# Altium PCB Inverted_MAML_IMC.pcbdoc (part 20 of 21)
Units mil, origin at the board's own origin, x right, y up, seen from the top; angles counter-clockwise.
Board outline 7677.1 x 6771.6 mil, 6 copper layers (Top Layer, Inner1, Inner2, Inner3, Inner4, Bottom Layer), stack 60.7 mil thick; 2732 components, 1531 nets, 7765 pads, 3705 vias.
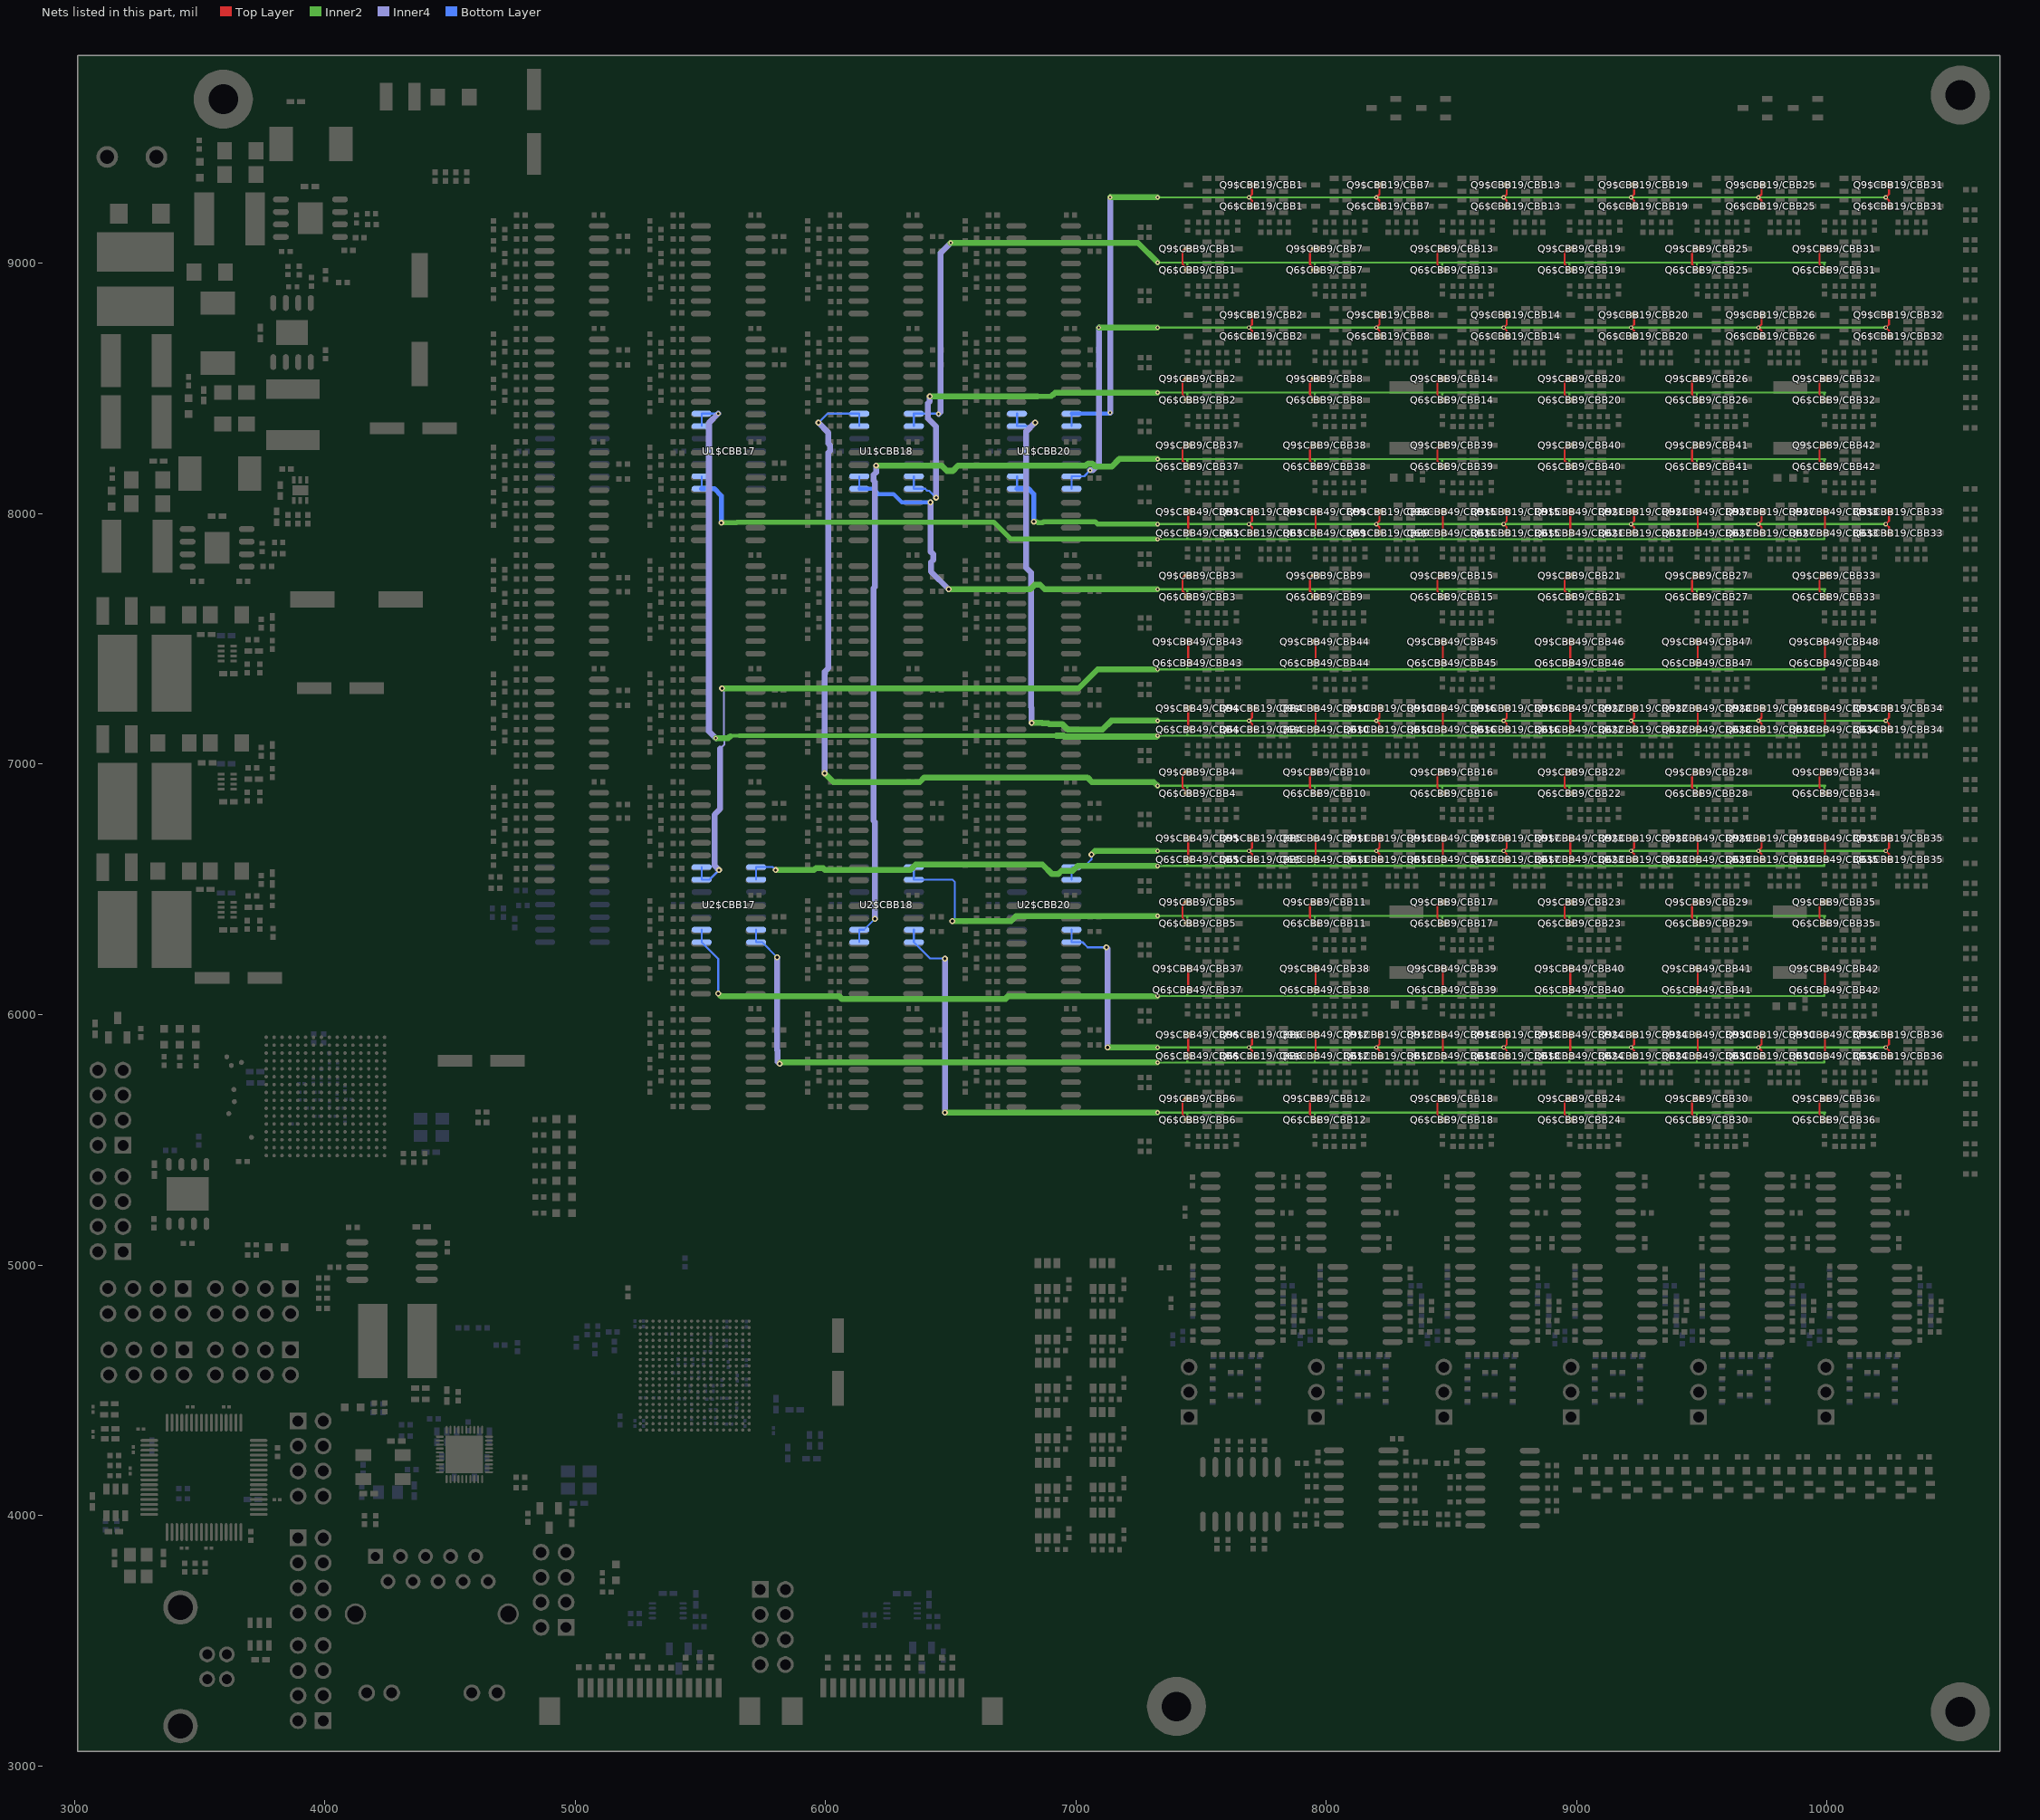
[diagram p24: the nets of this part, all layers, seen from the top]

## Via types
v1: diameter 17.7, hole 7.9, Top Layer to Bottom Layer, 3373 vias
v2: diameter 13.8, hole 7.9, Top Layer to Bottom Layer, 287 vias
v3: diameter 23.6, hole 11.8, Top Layer to Bottom Layer, 45 vias

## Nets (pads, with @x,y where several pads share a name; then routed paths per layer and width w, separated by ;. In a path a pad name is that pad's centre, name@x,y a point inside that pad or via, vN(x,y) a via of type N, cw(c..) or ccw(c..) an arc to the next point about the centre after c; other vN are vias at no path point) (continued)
W_M1_ROW3: Q6$CBB49/CBB3.3 Q6$CBB49/CBB9.3 Q6$CBB49/CBB15.3 Q6$CBB49/CBB21.3 Q6$CBB49/CBB27.3 Q6$CBB49/CBB33.3 Q9$CBB49/CBB3.3 Q9$CBB49/CBB9.3 Q9$CBB49/CBB15.3 Q9$CBB49/CBB21.3 Q9$CBB49/CBB27.3 Q9$CBB49/CBB33.3 U1$CBB17.8 U1$CBB17.9 | length 5355.6
  Top Layer w7.9: v1(7445.3,7923.7) 7448.8,7927.2 7448.8,7969 7448.4,7969.4 7448.4,7984.2 7448.8,7984.6 Q9$CBB49/CBB3.3@7448.8,8008.7 ; v1(7954,7923.7) 7957.5,7927.2 7957.5,7969 7957.1,7969.4 7957.1,7984.2 7957.5,7984.6 Q9$CBB49/CBB9.3@7957.5,8008.7 ; v1(8462.7,7923.7) 8466.2,7927.2 8466.2,7969 8465.8,7969.4 8465.8,7984.1 8466.2,7984.5 Q9$CBB49/CBB15.3@8466.2,8008.7 ; v1(8971.4,7923.7) 8974.9,7927.2 8974.9,7969 8974.5,7969.4 8974.5,7984.2 8974.9,7984.6 Q9$CBB49/CBB21.3@8974.9,8008.7 ; v1(9480.1,7923.7) 9483.6,7927.2 9483.6,7969 9483.2,7969.4 9483.2,7984.2 9483.6,7984.6 Q9$CBB49/CBB27.3@9483.6,8008.7 ; v1(9988.8,7923.7) 9992.3,7927.2 9992.3,7969 9991.9,7969.4 9991.9,7984.2 9992.3,7984.6 Q9$CBB49/CBB33.3@9992.3,8008.7
  Inner2 w7.9: v1(7326.2,7898.7) 7445.9,7898.7 ; v1(7445.3,7923.7) 7445.3,7899.3 7445.9,7898.7 ; v1(7954,7923.7) 7954,7899.3 7954.6,7898.7 ; v1(8462.7,7923.7) 8462.7,7899.3 8463.2,7898.7 ; v1(8971.4,7923.7) 8971.4,7899.3 8972,7898.7 ; v1(9480.1,7923.7) 9480.1,7899.3 9480.7,7898.7 ; v1(9988.8,7923.7) 9988.8,7899.3 9989.4,7898.7 9480.7,7898.7 ; 7445.9,7898.7 7954.6,7898.7 ; 7954.6,7898.7 8463.2,7898.7 ; 8463.2,7898.7 8972,7898.7 ; 8972,7898.7 9480.7,7898.7
  Inner2 w19.7: v3(5583.9,7963.7) 5644.1,7963.7 5647.3,7966.9 6671.8,7966.9 6740,7898.7 v1(7326.2,7898.7)
  Bottom Layer w7.9: U1$CBB17.8@5505.4,8100.1 U1$CBB17.9@5505.4,8150.1
  Bottom Layer w19.7: U1$CBB17.8@5505.4,8100.1 5555.8,8100.1 5583.9,8072 v3(5583.9,7963.7)
W_M1_ROW4: Q6$CBB49/CBB4.3 Q6$CBB49/CBB10.3 Q6$CBB49/CBB16.3 Q6$CBB49/CBB22.3 Q6$CBB49/CBB28.3 Q6$CBB49/CBB34.3 Q9$CBB49/CBB4.3 Q9$CBB49/CBB10.3 Q9$CBB49/CBB16.3 Q9$CBB49/CBB22.3 Q9$CBB49/CBB28.3 Q9$CBB49/CBB34.3 U1$CBB17.13 U1$CBB17.14 | length 6543.5
  Top Layer w7.9: v1(7445.3,7138.7) 7448.8,7142.2 7448.8,7184 7448.4,7184.4 7448.4,7199.2 7448.8,7199.6 Q9$CBB49/CBB4.3@7448.8,7223.7 ; v1(7954,7138.7) 7957.5,7142.2 7957.5,7184 7957.1,7184.4 7957.1,7199.2 7957.5,7199.6 Q9$CBB49/CBB10.3@7957.5,7223.7 ; v1(8462.7,7138.7) 8466.2,7142.2 8466.2,7184 8465.8,7184.4 8465.8,7199.1 8466.2,7199.5 Q9$CBB49/CBB16.3@8466.2,7223.7 ; v1(8971.4,7138.7) 8974.9,7142.2 8974.9,7184 8974.5,7184.4 8974.5,7199.2 8974.9,7199.6 Q9$CBB49/CBB22.3@8974.9,7223.7 ; v1(9480.1,7138.7) 9483.6,7142.2 9483.6,7184 9483.2,7184.4 9483.2,7199.2 9483.6,7199.6 Q9$CBB49/CBB28.3@9483.6,7223.7 ; v1(9988.8,7138.7) 9992.3,7142.2 9992.3,7184 9991.9,7184.4 9991.9,7199.2 9992.3,7199.6 Q9$CBB49/CBB34.3@9992.3,7223.7
  Inner2 w7.9: v1(7326.2,7113.7) 7445.9,7113.7 ; v1(7445.3,7138.7) 7445.3,7114.3 7445.9,7113.7 ; v1(7954,7138.7) 7954,7114.3 7954.6,7113.7 ; v1(8462.7,7138.7) 8462.7,7114.3 8463.2,7113.7 ; v1(8971.4,7138.7) 8971.4,7114.3 8972,7113.7 ; v1(9480.1,7138.7) 9480.1,7114.3 9480.7,7113.7 ; v1(9988.8,7138.7) 9988.8,7114.3 9989.4,7113.7 9480.7,7113.7 ; 7445.9,7113.7 7954.6,7113.7 ; 7954.6,7113.7 8463.2,7113.7 ; 8463.2,7113.7 8972,7113.7 ; 8972,7113.7 9480.7,7113.7
  Inner2 w15.7: 5622.1,7113.7 5657.1,7113.7
  Inner2 w19.7: 5657.1,7113.7 6922.1,7113.7
  Inner2 w23.6: v1(5562.1,7103.7) 5612.1,7103.7 5620.1,7111.7 ; 6922.1,7113.7 6951.6,7113.7 6955.3,7110.1 7322.6,7110.1 v1(7326.2,7113.7)
  Inner4 w23.6: v1(5562.1,7103.7) 5534.8,7131.1 5534.8,8362.7 v1(5572.1,8400.1)
  Bottom Layer w7.9: U1$CBB17.13@5505.4,8350.1 U1$CBB17.14@5505.4,8400.1 v1(5572.1,8400.1)
W_M1_ROW5: Q6$CBB49/CBB5.3 Q6$CBB49/CBB11.3 Q6$CBB49/CBB17.3 Q6$CBB49/CBB23.3 Q6$CBB49/CBB29.3 Q6$CBB49/CBB35.3 Q9$CBB49/CBB5.3 Q9$CBB49/CBB11.3 Q9$CBB49/CBB17.3 Q9$CBB49/CBB23.3 Q9$CBB49/CBB29.3 Q9$CBB49/CBB35.3 U2$CBB17.1 U2$CBB17.2 | length 5038.7
  Top Layer w7.9: v1(7445.3,6618.7) 7448.8,6622.2 7448.8,6664 7448.4,6664.4 7448.4,6679.2 7448.8,6679.6 Q9$CBB49/CBB5.3@7448.8,6703.7 ; v1(7954,6618.7) 7957.5,6622.2 7957.5,6664 7957.1,6664.4 7957.1,6679.2 7957.5,6679.6 Q9$CBB49/CBB11.3@7957.5,6703.7 ; v1(8462.7,6618.7) 8466.2,6622.2 8466.2,6664 8465.8,6664.4 8465.8,6679.1 8466.2,6679.5 Q9$CBB49/CBB17.3@8466.2,6703.7 ; v1(8971.4,6618.7) 8974.9,6622.2 8974.9,6664 8974.5,6664.4 8974.5,6679.2 8974.9,6679.6 Q9$CBB49/CBB23.3@8974.9,6703.7 ; v1(9480.1,6618.7) 9483.6,6622.2 9483.6,6664 9483.2,6664.4 9483.2,6679.2 9483.6,6679.6 Q9$CBB49/CBB29.3@9483.6,6703.7 ; v1(9988.8,6618.7) 9992.3,6622.2 9992.3,6664 9991.9,6664.4 9991.9,6679.2 9992.3,6679.6 Q9$CBB49/CBB35.3@9992.3,6703.7
  Inner2 w7.9: v1(7326.2,6593.7) 7445.9,6593.7 ; v1(7445.3,6618.7) 7445.3,6594.3 7445.9,6593.7 ; v1(7954,6618.7) 7954,6594.3 7954.6,6593.7 ; v1(8462.7,6618.7) 8462.7,6594.3 8463.2,6593.7 ; v1(8971.4,6618.7) 8971.4,6594.3 8972,6593.7 ; v1(9480.1,6618.7) 9480.1,6594.3 9480.7,6593.7 ; v1(9988.8,6618.7) 9988.8,6594.3 9989.4,6593.7 9480.7,6593.7 ; 7445.9,6593.7 7954.6,6593.7 ; 7954.6,6593.7 8463.2,6593.7 ; 8463.2,6593.7 8972,6593.7 ; 8972,6593.7 9480.7,6593.7
  Inner2 w23.6: v3(5800.7,6577) 5953.6,6577 5961.8,6585.3 5991.2,6585.3 5999.4,6577 6338.3,6577 6360.1,6598.9 6866.8,6598.9 6904.9,6560.7 6929,6560.7 6942.1,6573.7 6987.1,6573.7 7007.1,6593.7 v1(7326.2,6593.7)
  Bottom Layer w7.9: U2$CBB17.2@5723.4,6539.1 U2$CBB17.1@5723.4,6589.1 5788.7,6589.1 v3(5800.7,6577)
W_M1_ROW6: Q6$CBB49/CBB6.3 Q6$CBB49/CBB12.3 Q6$CBB49/CBB18.3 Q6$CBB49/CBB24.3 Q6$CBB49/CBB30.3 Q6$CBB49/CBB36.3 Q9$CBB49/CBB6.3 Q9$CBB49/CBB12.3 Q9$CBB49/CBB18.3 Q9$CBB49/CBB24.3 Q9$CBB49/CBB30.3 Q9$CBB49/CBB36.3 U2$CBB17.6 U2$CBB17.7 | length 5434.4
  Top Layer w7.9: v1(7445.3,5833.7) 7448.8,5837.2 7448.8,5879 7448.4,5879.4 7448.4,5894.2 7448.8,5894.6 Q9$CBB49/CBB6.3@7448.8,5918.7 ; v1(7954,5833.7) 7957.5,5837.2 7957.5,5879 7957.1,5879.4 7957.1,5894.2 7957.5,5894.6 Q9$CBB49/CBB12.3@7957.5,5918.7 ; v1(8462.7,5833.7) 8466.2,5837.2 8466.2,5879 8465.8,5879.4 8465.8,5894.1 8466.2,5894.5 Q9$CBB49/CBB18.3@8466.2,5918.7 ; v1(8971.4,5833.7) 8974.9,5837.2 8974.9,5879 8974.5,5879.4 8974.5,5894.2 8974.9,5894.6 Q9$CBB49/CBB24.3@8974.9,5918.7 ; v1(9480.1,5833.7) 9483.6,5837.2 9483.6,5879 9483.2,5879.4 9483.2,5894.2 9483.6,5894.6 Q9$CBB49/CBB30.3@9483.6,5918.7 ; v1(9988.8,5833.7) 9992.3,5837.2 9992.3,5879 9991.9,5879.4 9991.9,5894.2 9992.3,5894.6 Q9$CBB49/CBB36.3@9992.3,5918.7
  Inner2 w7.9: v1(7326.2,5808.7) 7445.9,5808.7 ; v1(7445.3,5833.7) 7445.3,5809.3 7445.9,5808.7 ; v1(7954,5833.7) 7954,5809.3 7954.6,5808.7 ; v1(8462.7,5833.7) 8462.7,5809.3 8463.2,5808.7 ; v1(8971.4,5833.7) 8971.4,5809.3 8972,5808.7 ; v1(9480.1,5833.7) 9480.1,5809.3 9480.7,5808.7 ; v1(9988.8,5833.7) 9988.8,5809.3 9989.4,5808.7 9480.7,5808.7 ; 7445.9,5808.7 7954.6,5808.7 ; 7954.6,5808.7 8463.2,5808.7 ; 8463.2,5808.7 8972,5808.7 ; 8972,5808.7 9480.7,5808.7
  Inner2 w23.6: v3(5817.1,5803.7) 5822.1,5808.7 v1(7326.2,5808.7)
  Inner4 w23.6: v3(5807.1,6228.7) 5807.1,5858.8 5809.3,5856.6 5809.3,5811.5 v3(5817.1,5803.7)
  Bottom Layer w7.9: U2$CBB17.6@5723.4,6339.1 U2$CBB17.7@5723.4,6289.1 5746.8,6289.1 v3(5807.1,6228.7)
W_M1_ROW7: Q6$CBB49/CBB37.3 Q6$CBB49/CBB38.3 Q6$CBB49/CBB39.3 Q6$CBB49/CBB40.3 Q6$CBB49/CBB41.3 Q6$CBB49/CBB42.3 Q9$CBB49/CBB37.3 Q9$CBB49/CBB38.3 Q9$CBB49/CBB39.3 Q9$CBB49/CBB40.3 Q9$CBB49/CBB41.3 Q9$CBB49/CBB42.3 U2$CBB17.8 U2$CBB17.9 | length 5386.7
  Top Layer w7.9: v1(7445.3,6098.7) 7448.8,6102.2 7448.8,6144 7448.4,6144.4 7448.4,6159.2 7448.8,6159.6 Q9$CBB49/CBB37.3@7448.8,6183.7 ; v1(7954,6098.7) 7957.5,6102.2 7957.5,6144 7957.1,6144.4 7957.1,6159.2 7957.5,6159.6 Q9$CBB49/CBB38.3@7957.5,6183.7 ; v1(8462.7,6098.7) 8466.2,6102.2 8466.2,6144 8465.8,6144.4 8465.8,6159.2 8466.2,6159.6 Q9$CBB49/CBB39.3@8466.2,6183.7 ; v1(8971.4,6098.7) 8974.9,6102.2 8974.9,6144 8974.5,6144.4 8974.5,6159.2 8974.9,6159.6 Q9$CBB49/CBB40.3@8974.9,6183.7 ; v1(9480.1,6098.7) 9483.6,6102.2 9483.6,6144 9483.2,6144.4 9483.2,6159.2 9483.6,6159.6 Q9$CBB49/CBB41.3@9483.6,6183.7 ; v1(9988.8,6098.7) 9992.3,6102.2 9992.3,6144 9991.9,6144.4 9991.9,6159.2 9992.3,6159.6 Q9$CBB49/CBB42.3@9992.3,6183.7
  Inner2 w7.9: v1(7326.2,6073.7) 7445.9,6073.7 ; v1(7445.3,6098.7) 7445.3,6074.3 7445.9,6073.7 ; v1(7954,6098.7) 7954,6074.3 7954.6,6073.7 ; v1(8462.7,6098.7) 8462.7,6074.3 8463.3,6073.7 ; v1(8971.4,6098.7) 8971.4,6074.3 8972,6073.7 ; v1(9480.1,6098.7) 9480.1,6074.3 9480.7,6073.7 ; v1(9988.8,6098.7) 9988.8,6074.3 9989.4,6073.7 9480.7,6073.7 ; 7445.9,6073.7 7954.6,6073.7 ; 7954.6,6073.7 8463.3,6073.7 ; 8463.3,6073.7 8972,6073.7 ; 8972,6073.7 9480.7,6073.7
  Inner2 w23.6: v3(5572.1,6083.7) 5582.1,6073.7 6054.2,6073.7 6066.4,6061.5 6541.3,6061.5 6542.8,6063.1 6719.1,6063.1 6729.8,6073.7 v1(7326.2,6073.7)
  Bottom Layer w7.9: U2$CBB17.9@5505.4,6339.1 U2$CBB17.8@5505.4,6289.1 5572.1,6222.3 v3(5572.1,6083.7)
W_M1_ROW8: Q6$CBB49/CBB43.3 Q6$CBB49/CBB44.3 Q6$CBB49/CBB45.3 Q6$CBB49/CBB46.3 Q6$CBB49/CBB47.3 Q6$CBB49/CBB48.3 Q9$CBB49/CBB43.3 Q9$CBB49/CBB44.3 Q9$CBB49/CBB45.3 Q9$CBB49/CBB46.3 Q9$CBB49/CBB47.3 Q9$CBB49/CBB48.3 U2$CBB17.13 U2$CBB17.14 | length 5994.6
  Top Layer w7.9: v1(7445.3,7403.7) 7448.8,7407.2 7448.8,7449 7448.4,7449.4 7448.4,7464.2 7448.8,7464.6 Q9$CBB49/CBB43.3@7448.8,7488.7 ; v1(7954,7403.7) 7957.5,7407.2 7957.5,7449 7957.1,7449.4 7957.1,7464.2 7957.5,7464.6 Q9$CBB49/CBB44.3@7957.5,7488.7 ; v1(8462.7,7403.7) 8466.2,7407.2 8466.2,7449 8465.8,7449.4 8465.8,7464.2 8466.2,7464.6 Q9$CBB49/CBB45.3@8466.2,7488.7 ; v1(8971.4,7403.7) 8974.9,7407.2 8974.9,7449 8974.5,7449.4 8974.5,7464.2 8974.9,7464.6 Q9$CBB49/CBB46.3@8974.9,7488.7 ; v1(9480.1,7403.7) 9483.6,7407.2 9483.6,7449 9483.2,7449.4 9483.2,7464.2 9483.6,7464.6 Q9$CBB49/CBB47.3@9483.6,7488.7 ; v1(9988.8,7403.7) 9992.3,7407.2 9992.3,7449 9991.9,7449.4 9991.9,7464.2 9992.3,7464.6 Q9$CBB49/CBB48.3@9992.3,7488.7
  Inner2 w7.9: v1(7326.2,7378.7) 7445.9,7378.7 ; v1(7445.3,7403.7) 7445.3,7379.3 7445.9,7378.7 ; v1(7954,7403.7) 7954,7379.3 7954.6,7378.7 ; v1(8462.7,7403.7) 8462.7,7379.3 8463.3,7378.7 ; v1(8971.4,7403.7) 8971.4,7379.3 8972,7378.7 ; v1(9480.1,7403.7) 9480.1,7379.3 9480.7,7378.7 ; v1(9988.8,7403.7) 9988.8,7379.3 9989.4,7378.7 9480.7,7378.7 ; 7445.9,7378.7 7954.6,7378.7 ; 7954.6,7378.7 8463.3,7378.7 ; 8463.3,7378.7 8972,7378.7 ; 8972,7378.7 9480.7,7378.7
  Inner2 w23.6: v3(5586.9,7302.8) 7011.2,7302.8 7087.1,7378.7 v1(7326.2,7378.7)
  Inner4 w7.9: 5579.5,7061.4 5596.3,7078.2 5596.3,7112.8 5594.7,7114.3 5594.7,7295 v3(5586.9,7302.8)
  Inner4 w23.6: v3(5574.9,6577) 5557.1,6594.8 5557.1,6798.7 5579.5,6821.1 5579.5,7061.4
  Bottom Layer w7.9: U2$CBB17.14@5505.4,6589.1 U2$CBB17.13@5505.4,6539.1 5536.9,6539.1 v3(5574.9,6577)
W_M2_ROW1: Q6$CBB9/CBB1.3 Q6$CBB9/CBB7.3 Q6$CBB9/CBB13.3 Q6$CBB9/CBB19.3 Q6$CBB9/CBB25.3 Q6$CBB9/CBB31.3 Q9$CBB9/CBB1.3 Q9$CBB9/CBB7.3 Q9$CBB9/CBB13.3 Q9$CBB9/CBB19.3 Q9$CBB9/CBB25.3 Q9$CBB9/CBB31.3 U1$CBB18.1 U1$CBB18.2 | length 5258.8
  Top Layer w7.9: v1(7445.3,8973.5) 7448.5,8973.5 Q6$CBB9/CBB1.3@7448.8,8973.7 7426.2,8996.3 7426.2,9048.7 7436.2,9058.7 Q9$CBB9/CBB1.3@7448.8,9058.7 ; v1(7954,8973.5) 7957.2,8973.5 Q6$CBB9/CBB7.3@7957.5,8973.7 7934.9,8996.3 7934.9,9048.7 7944.9,9058.7 Q9$CBB9/CBB7.3@7957.5,9058.7 ; v1(8462.7,8973.4) 8465.9,8973.4 Q6$CBB9/CBB13.3@8466.2,8973.7 8443.6,8996.3 8443.6,9048.7 8453.6,9058.7 Q9$CBB9/CBB13.3@8466.2,9058.7 ; v1(8971.4,8973.5) 8974.6,8973.5 Q6$CBB9/CBB19.3@8974.9,8973.7 8952.3,8996.3 8952.3,9048.7 8962.3,9058.7 Q9$CBB9/CBB19.3@8974.9,9058.7 ; v1(9480.1,8973.5) 9483.3,8973.5 Q6$CBB9/CBB25.3@9483.6,8973.7 9461,8996.3 9461,9048.7 9471,9058.7 Q9$CBB9/CBB25.3@9483.6,9058.7 ; v1(9988.8,8973.5) 9992,8973.5 Q6$CBB9/CBB31.3@9992.3,8973.7 9969.7,8996.3 9969.7,9048.7 9979.7,9058.7 Q9$CBB9/CBB31.3@9992.3,9058.7
  Inner2 w7.9: v1(7326.2,9003.7) 7449.8,9003.7 ; v1(7445.3,8973.5) 7445.3,8999.2 7449.8,9003.7 ; v1(7954,8973.5) 7954,8999.2 7958.5,9003.7 ; v1(8462.7,8973.4) 8462.7,8999.1 8467.2,9003.7 ; v1(8971.4,8973.5) 8971.4,8999.2 8975.9,9003.7 ; v1(9480.1,8973.5) 9480.1,8999.2 9484.6,9003.7 ; v1(9988.8,8973.5) 9988.8,8999.2 9993.3,9003.7 9484.6,9003.7 ; 7449.8,9003.7 7958.5,9003.7 ; 7958.5,9003.7 8975.9,9003.7 ; 8975.9,9003.7 9484.6,9003.7
  Inner2 w23.6: v1(6500.3,9082.1) 6500.6,9081.8 7248.1,9081.8 v1(7326.2,9003.7)
  Inner4 w23.6: v1(6452.1,8398.7) 6459.5,8406.1 6459.5,9041.3 v1(6500.3,9082.1)
  Bottom Layer w7.9: U1$CBB18.2@6353.3,8350.1 U1$CBB18.1@6353.3,8400.1 6450.8,8400.1 v1(6452.1,8398.7)
W_M2_ROW2: Q6$CBB9/CBB2.3 Q6$CBB9/CBB8.3 Q6$CBB9/CBB14.3 Q6$CBB9/CBB20.3 Q6$CBB9/CBB26.3 Q6$CBB9/CBB32.3 Q9$CBB9/CBB2.3 Q9$CBB9/CBB8.3 Q9$CBB9/CBB14.3 Q9$CBB9/CBB20.3 Q9$CBB9/CBB26.3 Q9$CBB9/CBB32.3 U1$CBB18.6 U1$CBB18.7 | length 5037.4
  Top Layer w7.9: v1(7445.3,8453.5) 7448.5,8453.5 Q6$CBB9/CBB2.3@7448.8,8453.7 7426.2,8476.3 7426.2,8528.7 7436.2,8538.7 Q9$CBB9/CBB2.3@7448.8,8538.7 ; v1(7954,8453.5) 7957.2,8453.5 Q6$CBB9/CBB8.3@7957.5,8453.7 7934.9,8476.3 7934.9,8528.7 7944.9,8538.7 Q9$CBB9/CBB8.3@7957.5,8538.7 ; v1(8462.7,8453.4) 8465.9,8453.4 Q6$CBB9/CBB14.3@8466.2,8453.7 8443.6,8476.3 8443.6,8528.7 8453.6,8538.7 Q9$CBB9/CBB14.3@8466.2,8538.7 ; v1(8971.4,8453.5) 8974.6,8453.5 Q6$CBB9/CBB20.3@8974.9,8453.7 8952.3,8476.3 8952.3,8528.7 8962.3,8538.7 Q9$CBB9/CBB20.3@8974.9,8538.7 ; v1(9480.1,8453.5) 9483.3,8453.5 Q6$CBB9/CBB26.3@9483.6,8453.7 9461,8476.3 9461,8528.7 9471,8538.7 Q9$CBB9/CBB26.3@9483.6,8538.7 ; v1(9988.8,8453.5) 9992,8453.5 Q6$CBB9/CBB32.3@9992.3,8453.7 9969.7,8476.3 9969.7,8528.7 9979.7,8538.7 Q9$CBB9/CBB32.3@9992.3,8538.7
  Inner2 w7.9: v1(7326.2,8483.7) 7449.8,8483.7 ; v1(7445.3,8453.5) 7445.3,8479.2 7449.8,8483.7 ; v1(7954,8453.5) 7954,8479.2 7958.5,8483.7 ; v1(8462.7,8453.4) 8462.7,8479.1 8467.2,8483.7 ; v1(8971.4,8453.5) 8971.4,8479.2 8975.9,8483.7 ; v1(9480.1,8453.5) 9480.1,8479.2 9484.6,8483.7 ; v1(9988.8,8453.5) 9988.8,8479.2 9993.3,8483.7 9484.6,8483.7 ; 7449.8,8483.7 7958.5,8483.7 ; 7958.5,8483.7 8975.9,8483.7 ; 8975.9,8483.7 9484.6,8483.7
  Inner2 w19.7: 6847.1,8468.7 6902.1,8468.7 6907.1,8473.7
  Inner2 w23.6: v3(6417.1,8468.7) 6847.1,8468.7 ; 6907.1,8473.7 6917.1,8483.7 v1(7326.2,8483.7)
  Inner4 w23.6: v3(6417.1,8468.7) 6417.1,8449.2 6409.1,8441.2 6409.1,8381.2 6442.1,8348.1 v3(6442.1,8064.7)
  Bottom Layer w7.9: U1$CBB18.6@6353.3,8150.1 U1$CBB18.7@6353.3,8100.1 6398.1,8100.1 6406.2,8092 6414.9,8092 v3(6442.1,8064.7)
W_M2_ROW3: Q6$CBB9/CBB3.3 Q6$CBB9/CBB9.3 Q6$CBB9/CBB15.3 Q6$CBB9/CBB21.3 Q6$CBB9/CBB27.3 Q6$CBB9/CBB33.3 Q9$CBB9/CBB3.3 Q9$CBB9/CBB9.3 Q9$CBB9/CBB15.3 Q9$CBB9/CBB21.3 Q9$CBB9/CBB27.3 Q9$CBB9/CBB33.3 U1$CBB18.8 U1$CBB18.9 | length 5138.2
  Top Layer w7.9: v1(7445.3,7668.5) 7448.5,7668.5 Q6$CBB9/CBB3.3@7448.8,7668.7 7426.2,7691.3 7426.2,7743.7 7436.2,7753.7 Q9$CBB9/CBB3.3@7448.8,7753.7 ; v1(7954,7668.5) 7957.2,7668.5 Q6$CBB9/CBB9.3@7957.5,7668.7 7934.9,7691.3 7934.9,7743.7 7944.9,7753.7 Q9$CBB9/CBB9.3@7957.5,7753.7 ; v1(8462.7,7668.4) 8465.9,7668.4 Q6$CBB9/CBB15.3@8466.2,7668.7 8443.6,7691.3 8443.6,7743.7 8453.6,7753.7 Q9$CBB9/CBB15.3@8466.2,7753.7 ; v1(8971.4,7668.5) 8974.6,7668.5 Q6$CBB9/CBB21.3@8974.9,7668.7 8952.3,7691.3 8952.3,7743.7 8962.3,7753.7 Q9$CBB9/CBB21.3@8974.9,7753.7 ; v1(9480.1,7668.5) 9483.3,7668.5 Q6$CBB9/CBB27.3@9483.6,7668.7 9461,7691.3 9461,7743.7 9471,7753.7 Q9$CBB9/CBB27.3@9483.6,7753.7 ; v1(9988.8,7668.5) 9992,7668.5 Q6$CBB9/CBB33.3@9992.3,7668.7 9969.7,7691.3 9969.7,7743.7 9979.7,7753.7 Q9$CBB9/CBB33.3@9992.3,7753.7
  Inner2 w7.9: v1(7326.2,7698.7) 7449.8,7698.7 ; v1(7445.3,7668.5) 7445.3,7694.2 7449.8,7698.7 ; v1(7954,7668.5) 7954,7694.2 7958.5,7698.7 ; v1(8462.7,7668.4) 8462.7,7694.1 8467.2,7698.7 ; v1(8971.4,7668.5) 8971.4,7694.2 8975.9,7698.7 ; v1(9480.1,7668.5) 9480.1,7694.2 9484.6,7698.7 ; v1(9988.8,7668.5) 9988.8,7694.2 9993.3,7698.7 9484.6,7698.7 ; 7449.8,7698.7 7958.5,7698.7 ; 7958.5,7698.7 8975.9,7698.7 ; 8975.9,7698.7 9484.6,7698.7
  Inner2 w23.6: v3(6492.1,7698.7) 6818.1,7698.7 6836.3,7717 6857.6,7717 6875.9,7698.7 v1(7326.2,7698.7)
  Inner4 w23.6: v3(6419.2,8045.8) 6419.2,7849.6 6431.3,7837.5 6431.3,7816.3 6422.1,7807.1 6422.1,7768.7 v3(6492.1,7698.7)
  Bottom Layer w7.9: U1$CBB18.8@6135.3,8100.1 U1$CBB18.9@6135.3,8150.1
  Bottom Layer w15.7: U1$CBB18.8@6135.3,8100.1 6190.8,8100.1 6212.1,8078.7 6272.1,8078.7 6305.1,8045.8 v3(6419.2,8045.8)
W_M2_ROW4: Q6$CBB9/CBB4.3 Q6$CBB9/CBB10.3 Q6$CBB9/CBB16.3 Q6$CBB9/CBB22.3 Q6$CBB9/CBB28.3 Q6$CBB9/CBB34.3 Q9$CBB9/CBB4.3 Q9$CBB9/CBB10.3 Q9$CBB9/CBB16.3 Q9$CBB9/CBB22.3 Q9$CBB9/CBB28.3 Q9$CBB9/CBB34.3 U1$CBB18.13 U1$CBB18.14 | length 6569.6
  Top Layer w7.9: v1(7445.3,6883.5) 7448.5,6883.5 Q6$CBB9/CBB4.3@7448.8,6883.7 7426.2,6906.3 7426.2,6958.7 7436.2,6968.7 Q9$CBB9/CBB4.3@7448.8,6968.7 ; v1(7954,6883.5) 7957.2,6883.5 Q6$CBB9/CBB10.3@7957.5,6883.7 7934.9,6906.3 7934.9,6958.7 7944.9,6968.7 Q9$CBB9/CBB10.3@7957.5,6968.7 ; v1(8462.7,6883.4) 8465.9,6883.4 Q6$CBB9/CBB16.3@8466.2,6883.7 8443.6,6906.3 8443.6,6958.7 8453.6,6968.7 Q9$CBB9/CBB16.3@8466.2,6968.7 ; v1(8971.4,6883.5) 8974.6,6883.5 Q6$CBB9/CBB22.3@8974.9,6883.7 8952.3,6906.3 8952.3,6958.7 8962.3,6968.7 Q9$CBB9/CBB22.3@8974.9,6968.7 ; v1(9480.1,6883.5) 9483.3,6883.5 Q6$CBB9/CBB28.3@9483.6,6883.7 9461,6906.3 9461,6958.7 9471,6968.7 Q9$CBB9/CBB28.3@9483.6,6968.7 ; v1(9988.8,6883.5) 9992,6883.5 Q6$CBB9/CBB34.3@9992.3,6883.7 9969.7,6906.3 9969.7,6958.7 9979.7,6968.7 Q9$CBB9/CBB34.3@9992.3,6968.7
  Inner2 w7.9: v1(7326.2,6913.7) 7449.8,6913.7 ; v1(7445.3,6883.5) 7445.3,6909.2 7449.8,6913.7 ; v1(7954,6883.5) 7954,6909.2 7958.5,6913.7 ; v1(8462.7,6883.4) 8462.7,6909.1 8467.2,6913.7 ; v1(8971.4,6883.5) 8971.4,6909.2 8975.9,6913.7 ; v1(9480.1,6883.5) 9480.1,6909.2 9484.6,6913.7 ; v1(9988.8,6883.5) 9988.8,6909.2 9993.3,6913.7 9484.6,6913.7 ; 7449.8,6913.7 7958.5,6913.7 ; 7958.5,6913.7 8975.9,6913.7 ; 8975.9,6913.7 9484.6,6913.7
  Inner2 w23.6: v3(5997.2,6963.7) 6032.2,6928.7 6376.6,6928.7 6394.9,6947.1 7046.1,6947.1 7064.5,6928.7 7311.2,6928.7 v1(7326.2,6913.7)
  Inner4 w23.6: v3(5972.1,8363.8) 6012.1,8323.8 6012.1,8280.2 6019.3,8273 6019.3,8251.7 6012.1,8244.5 6012.1,7383.7 5997.7,7369.3 5997.7,7362.1 5997.2,7361.6 v3(5997.2,6963.7)
  Bottom Layer w7.9: v3(5972.1,8363.8) 6008.5,8400.1 U1$CBB18.14@6135.3,8400.1 U1$CBB18.13@6135.3,8350.1
W_M2_ROW5: Q6$CBB9/CBB5.3 Q6$CBB9/CBB11.3 Q6$CBB9/CBB17.3 Q6$CBB9/CBB23.3 Q6$CBB9/CBB29.3 Q6$CBB9/CBB35.3 Q9$CBB9/CBB5.3 Q9$CBB9/CBB11.3 Q9$CBB9/CBB17.3 Q9$CBB9/CBB23.3 Q9$CBB9/CBB29.3 Q9$CBB9/CBB35.3 U2$CBB18.1 U2$CBB18.2 | length 4752.3
  Top Layer w7.9: v1(7445.3,6363.5) 7448.5,6363.5 Q6$CBB9/CBB5.3@7448.8,6363.7 7426.2,6386.3 7426.2,6438.7 7436.2,6448.7 Q9$CBB9/CBB5.3@7448.8,6448.7 ; v1(7954,6363.5) 7957.2,6363.5 Q6$CBB9/CBB11.3@7957.5,6363.7 7934.9,6386.3 7934.9,6438.7 7944.9,6448.7 Q9$CBB9/CBB11.3@7957.5,6448.7 ; v1(8462.7,6363.4) 8465.9,6363.4 Q6$CBB9/CBB17.3@8466.2,6363.7 8443.6,6386.3 8443.6,6438.7 8453.6,6448.7 Q9$CBB9/CBB17.3@8466.2,6448.7 ; v1(8971.4,6363.5) 8974.6,6363.5 Q6$CBB9/CBB23.3@8974.9,6363.7 8952.3,6386.3 8952.3,6438.7 8962.3,6448.7 Q9$CBB9/CBB23.3@8974.9,6448.7 ; v1(9480.1,6363.5) 9483.3,6363.5 Q6$CBB9/CBB29.3@9483.6,6363.7 9461,6386.3 9461,6438.7 9471,6448.7 Q9$CBB9/CBB29.3@9483.6,6448.7 ; v1(9988.8,6363.5) 9992,6363.5 Q6$CBB9/CBB35.3@9992.3,6363.7 9969.7,6386.3 9969.7,6438.7 9979.7,6448.7 Q9$CBB9/CBB35.3@9992.3,6448.7
  Inner2 w7.9: v1(7326.2,6393.7) 7449.8,6393.7 ; v1(7445.3,6363.5) 7445.3,6389.2 7449.8,6393.7 ; v1(7954,6363.5) 7954,6389.2 7958.5,6393.7 ; v1(8462.7,6363.4) 8462.7,6389.1 8467.2,6393.7 ; v1(8971.4,6363.5) 8971.4,6389.2 8975.9,6393.7 ; v1(9480.1,6363.5) 9480.1,6389.2 9484.6,6393.7 ; v1(9988.8,6363.5) 9988.8,6389.2 9993.3,6393.7 9484.6,6393.7 ; 7449.8,6393.7 7958.5,6393.7 ; 7958.5,6393.7 8975.9,6393.7 ; 8975.9,6393.7 9484.6,6393.7
  Inner2 w23.6: v3(6507.1,6373.7) 6742.1,6373.7 6762.1,6393.7 v1(7326.2,6393.7)
  Bottom Layer w7.9: U2$CBB18.1@6353.3,6589.1 U2$CBB18.2@6353.3,6539.1 6506.8,6539.1 6517.1,6528.7 6517.1,6383.7 v3(6507.1,6373.7)
W_M2_ROW6: Q6$CBB9/CBB6.3 Q6$CBB9/CBB12.3 Q6$CBB9/CBB18.3 Q6$CBB9/CBB24.3 Q6$CBB9/CBB30.3 Q6$CBB9/CBB36.3 Q9$CBB9/CBB6.3 Q9$CBB9/CBB12.3 Q9$CBB9/CBB18.3 Q9$CBB9/CBB24.3 Q9$CBB9/CBB30.3 Q9$CBB9/CBB36.3 U2$CBB18.6 U2$CBB18.7 | length 5212.6
  Top Layer w7.9: v1(7445.3,5578.5) 7448.5,5578.5 Q6$CBB9/CBB6.3@7448.8,5578.7 7426.2,5601.3 7426.2,5653.7 7436.2,5663.7 Q9$CBB9/CBB6.3@7448.8,5663.7 ; v1(7954,5578.5) 7957.2,5578.5 Q6$CBB9/CBB12.3@7957.5,5578.7 7934.9,5601.3 7934.9,5653.7 7944.9,5663.7 Q9$CBB9/CBB12.3@7957.5,5663.7 ; v1(8462.7,5578.4) 8465.9,5578.4 Q6$CBB9/CBB18.3@8466.2,5578.7 8443.6,5601.3 8443.6,5653.7 8453.6,5663.7 Q9$CBB9/CBB18.3@8466.2,5663.7 ; v1(8971.4,5578.5) 8974.6,5578.5 Q6$CBB9/CBB24.3@8974.9,5578.7 8952.3,5601.3 8952.3,5653.7 8962.3,5663.7 Q9$CBB9/CBB24.3@8974.9,5663.7 ; v1(9480.1,5578.5) 9483.3,5578.5 Q6$CBB9/CBB30.3@9483.6,5578.7 9461,5601.3 9461,5653.7 9471,5663.7 Q9$CBB9/CBB30.3@9483.6,5663.7 ; v1(9988.8,5578.5) 9992,5578.5 Q6$CBB9/CBB36.3@9992.3,5578.7 9969.7,5601.3 9969.7,5653.7 9979.7,5663.7 Q9$CBB9/CBB36.3@9992.3,5663.7
  Inner2 w7.9: v1(7326.2,5608.7) 7449.8,5608.7 ; v1(7445.3,5578.5) 7445.3,5604.2 7449.8,5608.7 ; v1(7954,5578.5) 7954,5604.2 7958.5,5608.7 ; v1(8462.7,5578.4) 8462.7,5604.1 8467.2,5608.7 ; v1(8971.4,5578.5) 8971.4,5604.2 8975.9,5608.7 ; v1(9480.1,5578.5) 9480.1,5604.2 9484.6,5608.7 ; v1(9988.8,5578.5) 9988.8,5604.2 9993.3,5608.7 9484.6,5608.7 ; 7449.8,5608.7 7958.5,5608.7 ; 7958.5,5608.7 8975.9,5608.7 ; 8975.9,5608.7 9484.6,5608.7
  Inner2 w23.6: v3(6477.1,5608.7) v1(7326.2,5608.7)
  Inner4 w23.6: v3(6477.1,5608.7) v3(6477.1,6223.7)
  Bottom Layer w7.9: U2$CBB18.6@6353.3,6339.1 U2$CBB18.7@6353.3,6289.1 6418.7,6223.7 v3(6477.1,6223.7)
W_M2_ROW7: Q6$CBB9/CBB37.3 Q6$CBB9/CBB38.3 Q6$CBB9/CBB39.3 Q6$CBB9/CBB40.3 Q6$CBB9/CBB41.3 Q6$CBB9/CBB42.3 Q9$CBB9/CBB37.3 Q9$CBB9/CBB38.3 Q9$CBB9/CBB39.3 Q9$CBB9/CBB40.3 Q9$CBB9/CBB41.3 Q9$CBB9/CBB42.3 U2$CBB18.8 U2$CBB18.9 | length 6659.9
  Top Layer w7.9: v1(7445.3,8188.5) 7448.5,8188.5 Q6$CBB9/CBB37.3@7448.8,8188.7 7426.2,8211.3 7426.2,8263.7 7436.2,8273.7 Q9$CBB9/CBB37.3@7448.8,8273.7 ; v1(7954,8188.5) 7957.2,8188.5 Q6$CBB9/CBB38.3@7957.5,8188.7 7934.9,8211.3 7934.9,8263.7 7944.9,8273.7 Q9$CBB9/CBB38.3@7957.5,8273.7 ; v1(8462.7,8188.4) 8465.9,8188.4 Q6$CBB9/CBB39.3@8466.2,8188.7 8443.6,8211.3 8443.6,8263.7 8453.6,8273.7 Q9$CBB9/CBB39.3@8466.2,8273.7 ; v1(8971.4,8188.5) 8974.6,8188.5 Q6$CBB9/CBB40.3@8974.9,8188.7 8952.3,8211.3 8952.3,8263.7 8962.3,8273.7 Q9$CBB9/CBB40.3@8974.9,8273.7 ; v1(9480.1,8188.5) 9483.3,8188.5 Q6$CBB9/CBB41.3@9483.6,8188.7 9461,8211.3 9461,8263.7 9471,8273.7 Q9$CBB9/CBB41.3@9483.6,8273.7 ; v1(9988.8,8188.5) 9992,8188.5 Q6$CBB9/CBB42.3@9992.3,8188.7 9969.7,8211.3 9969.7,8263.7 9979.7,8273.7 Q9$CBB9/CBB42.3@9992.3,8273.7
  Inner2 w7.9: v1(7326.2,8218.7) 7449.8,8218.7 ; v1(7445.3,8188.5) 7445.3,8214.2 7449.8,8218.7 ; v1(7954,8188.5) 7954,8214.2 7958.5,8218.7 ; v1(8462.7,8188.4) 8462.7,8214.1 8467.2,8218.7 ; v1(8971.4,8188.5) 8971.4,8214.2 8975.9,8218.7 ; v1(9480.1,8188.5) 9480.1,8214.2 9484.6,8218.7 ; v1(9988.8,8188.5) 9988.8,8214.2 9993.3,8218.7 9484.6,8218.7 ; 7449.8,8218.7 7958.5,8218.7 ; 7958.5,8218.7 8975.9,8218.7 ; 8975.9,8218.7 9484.6,8218.7
  Inner2 w23.6: v3(6202.1,8193.1) 6463.7,8193.1 6485.3,8171.5 6509,8171.5 6530.6,8193.1 7040.2,8193.1 7046.5,8199.4 7067.8,8199.4 7079.1,8188.1 7142.8,8188.1 7173.4,8218.7 v1(7326.2,8218.7)
  Inner4 w23.6: v3(6197.1,6382.3) 6197.1,6769.4 6192.4,6774.1 6192.4,7703 6197.1,7707.7 6197.1,8127.7 6192.4,8132.4 6192.4,8155.8 6202.1,8165.5 v3(6202.1,8193.1)
  Bottom Layer w7.9: U2$CBB18.8@6135.3,6289.1 U2$CBB18.9@6135.3,6339.1 6153.9,6339.1 v3(6197.1,6382.3)
W_MA_ROW1: Q6$CBB19/CBB1.3 Q6$CBB19/CBB7.3 Q6$CBB19/CBB13.3 Q6$CBB19/CBB19.3 Q6$CBB19/CBB25.3 Q6$CBB19/CBB31.3 Q9$CBB19/CBB1.3 Q9$CBB19/CBB7.3 Q9$CBB19/CBB13.3 Q9$CBB19/CBB19.3 Q9$CBB19/CBB25.3 Q9$CBB19/CBB31.3 U1$CBB20.1 U1$CBB20.2 | length 4735.6
  Top Layer w7.9: Q6$CBB19/CBB1.3@7703.8,9228.7 7703.8,9251.1 v1(7691.2,9263.7) 7703.8,9276.3 Q9$CBB19/CBB1.3@7703.8,9313.7 ; Q6$CBB19/CBB7.3@8212.5,9228.7 8212.5,9251.1 v1(8199.9,9263.7) 8212.5,9276.3 Q9$CBB19/CBB7.3@8212.5,9313.7 ; Q6$CBB19/CBB13.3@8721.2,9228.7 8721.2,9251.1 v1(8708.6,9263.7) 8721.2,9276.3 Q9$CBB19/CBB13.3@8721.2,9313.7 ; Q6$CBB19/CBB19.3@9229.9,9228.7 9229.9,9251.1 v1(9217.3,9263.7) 9229.9,9276.3 Q9$CBB19/CBB19.3@9229.9,9313.7 ; Q6$CBB19/CBB25.3@9738.6,9228.7 9738.6,9251.1 v1(9726,9263.7) 9738.6,9276.3 Q9$CBB19/CBB25.3@9738.6,9313.7 ; Q6$CBB19/CBB31.3@10247.3,9228.7 10247.3,9251.1 v1(10234.7,9263.7) 10247.3,9276.3 Q9$CBB19/CBB31.3@10247.3,9313.7
  Inner2 w7.9: v1(7326.2,9263.7) v1(7691.2,9263.7) v1(8199.9,9263.7) v1(8708.6,9263.7) v1(9217.3,9263.7) v1(9726,9263.7) v1(10234.7,9263.7)
  Inner2 w23.6: v1(7137.1,9263.7) v1(7326.2,9263.7)
  Inner4 w23.6: v1(7137.1,8403.7) v1(7137.1,9263.7)
  Bottom Layer w7.9: U1$CBB20.2@6983.2,8350.1 U1$CBB20.1@6983.2,8400.1
  Bottom Layer w15.7: U1$CBB20.1@6983.2,8400.1 7133.5,8400.1 v1(7137.1,8403.7)
W_MA_ROW2: Q6$CBB19/CBB2.3 Q6$CBB19/CBB8.3 Q6$CBB19/CBB14.3 Q6$CBB19/CBB20.3 Q6$CBB19/CBB26.3 Q6$CBB19/CBB32.3 Q9$CBB19/CBB2.3 Q9$CBB19/CBB8.3 Q9$CBB19/CBB14.3 Q9$CBB19/CBB20.3 Q9$CBB19/CBB26.3 Q9$CBB19/CBB32.3 U1$CBB20.6 U1$CBB20.7 | length 4439.3
  Top Layer w7.9: Q6$CBB19/CBB2.3@7703.8,8708.7 7703.8,8731.1 v1(7691.2,8743.7) 7703.8,8756.3 Q9$CBB19/CBB2.3@7703.8,8793.7 ; Q6$CBB19/CBB8.3@8212.5,8708.7 8212.5,8731.1 v1(8199.9,8743.7) 8212.5,8756.3 Q9$CBB19/CBB8.3@8212.5,8793.7 ; Q6$CBB19/CBB14.3@8721.2,8708.7 8721.2,8731.1 v1(8708.6,8743.7) 8721.2,8756.3 Q9$CBB19/CBB14.3@8721.2,8793.7 ; Q6$CBB19/CBB20.3@9229.9,8708.7 9229.9,8731.1 v1(9217.3,8743.7) 9229.9,8756.3 Q9$CBB19/CBB20.3@9229.9,8793.7 ; Q6$CBB19/CBB26.3@9738.6,8708.7 9738.6,8731.1 v1(9726,8743.7) 9738.6,8756.3 Q9$CBB19/CBB26.3@9738.6,8793.7 ; Q6$CBB19/CBB32.3@10247.3,8708.7 10247.3,8731.1 v1(10234.7,8743.7) 10247.3,8756.3 Q9$CBB19/CBB32.3@10247.3,8793.7
  Inner2 w7.9: v1(7326.2,8743.7) v1(7691.2,8743.7) v1(8199.9,8743.7) v1(8708.6,8743.7) v1(9217.3,8743.7) v1(9726,8743.7) v1(10234.7,8743.7)
  Inner2 w23.6: v1(7092.1,8743.7) v1(7326.2,8743.7)
  Inner4 w23.6: v1(7057.1,8173.7) 7067.1,8173.7 7092.1,8198.7 v1(7092.1,8743.7)
  Bottom Layer w7.9: U1$CBB20.7@6983.2,8100.1 U1$CBB20.6@6983.2,8150.1 7033.5,8150.1 v1(7057.1,8173.7)
W_MA_ROW3: Q6$CBB19/CBB3.3 Q6$CBB19/CBB9.3 Q6$CBB19/CBB15.3 Q6$CBB19/CBB21.3 Q6$CBB19/CBB27.3 Q6$CBB19/CBB33.3 Q9$CBB19/CBB3.3 Q9$CBB19/CBB9.3 Q9$CBB19/CBB15.3 Q9$CBB19/CBB21.3 Q9$CBB19/CBB27.3 Q9$CBB19/CBB33.3 U1$CBB20.8 U1$CBB20.9 | length 4218.7
  Top Layer w7.9: Q6$CBB19/CBB3.3@7703.8,7923.7 7703.8,7946.1 v1(7691.2,7958.7) 7703.8,7971.3 Q9$CBB19/CBB3.3@7703.8,8008.7 ; Q6$CBB19/CBB9.3@8212.5,7923.7 8212.5,7946.1 v1(8199.9,7958.7) 8212.5,7971.3 Q9$CBB19/CBB9.3@8212.5,8008.7 ; Q6$CBB19/CBB15.3@8721.2,7923.7 8721.2,7946.1 v1(8708.6,7958.7) 8721.2,7971.3 Q9$CBB19/CBB15.3@8721.2,8008.7 ; Q6$CBB19/CBB21.3@9229.9,7923.7 9229.9,7946.1 v1(9217.3,7958.7) 9229.9,7971.3 Q9$CBB19/CBB21.3@9229.9,8008.7 ; Q6$CBB19/CBB27.3@9738.6,7923.7 9738.6,7946.1 v1(9726,7958.7) 9738.6,7971.3 Q9$CBB19/CBB27.3@9738.6,8008.7 ; Q6$CBB19/CBB33.3@10247.3,7923.7 10247.3,7946.1 v1(10234.7,7958.7) 10247.3,7971.3 Q9$CBB19/CBB33.3@10247.3,8008.7
  Inner2 w7.9: v1(7326.2,7958.7) v1(7691.2,7958.7) v1(8199.9,7958.7) v1(8708.6,7958.7) v1(9217.3,7958.7) v1(9726,7958.7) v1(10234.7,7958.7)
  Inner2 w19.7: v3(6832.1,7968.7) 6843.3,7968.7 6847.5,7964.5 6867.2,7964.5 6871.5,7968.7 6887.4,7968.7 6887.7,7968.5 6907.3,7968.5 6907.6,7968.7 7077.1,7968.7 7087.1,7958.7 v1(7326.2,7958.7)
  Bottom Layer w7.9: U1$CBB20.8@6765.2,8100.1 U1$CBB20.9@6765.2,8150.1
  Bottom Layer w19.7: U1$CBB20.8@6765.2,8100.1 6810.8,8100.1 6832.1,8078.7 v3(6832.1,7968.7)
W_MA_ROW4: Q6$CBB19/CBB4.3 Q6$CBB19/CBB10.3 Q6$CBB19/CBB16.3 Q6$CBB19/CBB22.3 Q6$CBB19/CBB28.3 Q6$CBB19/CBB34.3 Q9$CBB19/CBB4.3 Q9$CBB19/CBB10.3 Q9$CBB19/CBB16.3 Q9$CBB19/CBB22.3 Q9$CBB19/CBB28.3 Q9$CBB19/CBB34.3 U1$CBB20.13 U1$CBB20.14 | length 5359.2
  Top Layer w7.9: Q6$CBB19/CBB4.3@7703.8,7138.7 7703.8,7161.1 v1(7691.2,7173.7) 7703.8,7186.3 Q9$CBB19/CBB4.3@7703.8,7223.7 ; Q6$CBB19/CBB10.3@8212.5,7138.7 8212.5,7161.1 v1(8199.9,7173.7) 8212.5,7186.3 Q9$CBB19/CBB10.3@8212.5,7223.7 ; Q6$CBB19/CBB16.3@8721.2,7138.7 8721.2,7161.1 v1(8708.6,7173.7) 8721.2,7186.3 Q9$CBB19/CBB16.3@8721.2,7223.7 ; Q6$CBB19/CBB22.3@9229.9,7138.7 9229.9,7161.1 v1(9217.3,7173.7) 9229.9,7186.3 Q9$CBB19/CBB22.3@9229.9,7223.7 ; Q6$CBB19/CBB28.3@9738.6,7138.7 9738.6,7161.1 v1(9726,7173.7) 9738.6,7186.3 Q9$CBB19/CBB28.3@9738.6,7223.7 ; Q6$CBB19/CBB34.3@10247.3,7138.7 10247.3,7161.1 v1(10234.7,7173.7) 10247.3,7186.3 Q9$CBB19/CBB34.3@10247.3,7223.7
  Inner2 w7.9: v1(7326.2,7173.7) v1(7691.2,7173.7) v1(8199.9,7173.7) v1(8708.6,7173.7) v1(9217.3,7173.7) v1(9726,7173.7) v1(10234.7,7173.7)
  Inner2 w23.6: v3(6823.8,7164.5) 6864.8,7164.5 6866.2,7163.1 6890.5,7163.1 6893.2,7160.5 6945.4,7160.5 6967.1,7138.7 7107.1,7138.7 7142.1,7173.7 v1(7326.2,7173.7)
  Inner4 w23.6: v3(6823.8,7164.5) 6823.8,7225.5 6821.3,7227.9 6821.3,7764.6 6802.1,7783.7 6802.1,8328.8 v3(6837.1,8363.8)
  Bottom Layer w7.9: U1$CBB20.14@6765.2,8400.1 U1$CBB20.13@6765.2,8350.1 6823.5,8350.1 v3(6837.1,8363.8)
W_MA_ROW5: Q6$CBB19/CBB5.3 Q6$CBB19/CBB11.3 Q6$CBB19/CBB17.3 Q6$CBB19/CBB23.3 Q6$CBB19/CBB29.3 Q6$CBB19/CBB35.3 Q9$CBB19/CBB5.3 Q9$CBB19/CBB11.3 Q9$CBB19/CBB17.3 Q9$CBB19/CBB23.3 Q9$CBB19/CBB29.3 Q9$CBB19/CBB35.3 U2$CBB20.1 U2$CBB20.2 | length 3912.9
  Top Layer w7.9: Q6$CBB19/CBB5.3@7703.8,6618.7 7703.8,6641.1 v1(7691.2,6653.7) 7703.8,6666.3 Q9$CBB19/CBB5.3@7703.8,6703.7 ; Q6$CBB19/CBB11.3@8212.5,6618.7 8212.5,6641.1 v1(8199.9,6653.7) 8212.5,6666.3 Q9$CBB19/CBB11.3@8212.5,6703.7 ; Q6$CBB19/CBB17.3@8721.2,6618.7 8721.2,6641.1 v1(8708.6,6653.7) 8721.2,6666.3 Q9$CBB19/CBB17.3@8721.2,6703.7 ; Q6$CBB19/CBB23.3@9229.9,6618.7 9229.9,6641.1 v1(9217.3,6653.7) 9229.9,6666.3 Q9$CBB19/CBB23.3@9229.9,6703.7 ; Q6$CBB19/CBB29.3@9738.6,6618.7 9738.6,6641.1 v1(9726,6653.7) 9738.6,6666.3 Q9$CBB19/CBB29.3@9738.6,6703.7 ; Q6$CBB19/CBB35.3@10247.3,6618.7 10247.3,6641.1 v1(10234.7,6653.7) 10247.3,6666.3 Q9$CBB19/CBB35.3@10247.3,6703.7
  Inner2 w7.9: v1(7326.2,6653.7) v1(7691.2,6653.7) v1(8199.9,6653.7) v1(8708.6,6653.7) v1(9217.3,6653.7) v1(9726,6653.7) v1(10234.7,6653.7)
  Inner2 w23.6: v3@7062.1,6638.7 7077.1,6653.7 v1(7326.2,6653.7)
  Bottom Layer w7.9: U2$CBB20.2@6983.2,6539.1 U2$CBB20.1@6983.2,6589.1 7032.5,6589.1 7062.3,6618.9 v3(7062.3,6638.9)
W_MA_ROW6: Q6$CBB19/CBB6.3 Q6$CBB19/CBB12.3 Q6$CBB19/CBB18.3 Q6$CBB19/CBB24.3 Q6$CBB19/CBB30.3 Q6$CBB19/CBB36.3 Q9$CBB19/CBB6.3 Q9$CBB19/CBB12.3 Q9$CBB19/CBB18.3 Q9$CBB19/CBB24.3 Q9$CBB19/CBB30.3 Q9$CBB19/CBB36.3 U2$CBB20.6 U2$CBB20.7 | length 4279.7
  Top Layer w7.9: Q6$CBB19/CBB6.3@7703.8,5833.7 7703.8,5856.1 v1(7691.2,5868.7) 7703.8,5881.3 Q9$CBB19/CBB6.3@7703.8,5918.7 ; Q6$CBB19/CBB12.3@8212.5,5833.7 8212.5,5856.1 v1(8199.9,5868.7) 8212.5,5881.3 Q9$CBB19/CBB12.3@8212.5,5918.7 ; Q6$CBB19/CBB18.3@8721.2,5833.7 8721.2,5856.1 v1(8708.6,5868.7) 8721.2,5881.3 Q9$CBB19/CBB18.3@8721.2,5918.7 ; Q6$CBB19/CBB24.3@9229.9,5833.7 9229.9,5856.1 v1(9217.3,5868.7) 9229.9,5881.3 Q9$CBB19/CBB24.3@9229.9,5918.7 ; Q6$CBB19/CBB30.3@9738.6,5833.7 9738.6,5856.1 v1(9726,5868.7) 9738.6,5881.3 Q9$CBB19/CBB30.3@9738.6,5918.7 ; Q6$CBB19/CBB36.3@10247.3,5833.7 10247.3,5856.1 v1(10234.7,5868.7) 10247.3,5881.3 Q9$CBB19/CBB36.3@10247.3,5918.7
  Inner2 w7.9: v1(7326.2,5868.7) v1(7691.2,5868.7) v1(8199.9,5868.7) v1(8708.6,5868.7) v1(9217.3,5868.7) v1(9726,5868.7) v1(10234.7,5868.7)
  Inner2 w23.6: v3(7127.1,5868.7) v1(7326.2,5868.7)
  Inner4 w23.6: v3(7122.1,6268.7) 7127.1,6263.7 v3(7127.1,5868.7)
  Bottom Layer w7.9: U2$CBB20.6@6983.2,6339.1 U2$CBB20.7@6983.2,6289.1 7026.8,6289.1 7047.1,6268.7 v3(7122.1,6268.7)
pads on no net: D1$CBB24.4 D1$CBB24.6 FPC1$CBB22/CBB1.12 FPC3$CBB22/CBB1.12 U1$CBB22.5 U1$CBB22.6 U1$CBB22.7 U1$CBB22.8 U1$CBB23.A8 U1$CBB23.C5 U1$CBB23.C8 U1$CBB23.D8 U1$CBB23.D9 U1$CBB23.D10 U1$CBB23.E7 U1$CBB23.F2 U1$CBB23.G3 U1$CBB23.G5 U1$CBB23.G15 U1$CBB23.H5 U1$CBB23.H12 U1$CBB23.H13 U1$CBB23.H14 U1$CBB23.H15 U1$CBB23.H16 U1$CBB23.J4 U1$CBB23.J5 U1$CBB23.J12 U1$CBB23.J13 U1$CBB23.J14 U1$CBB23.J15 U1$CBB23.K14 U1$CBB23.K15 U1$CBB23.K16 U1$CBB23.L13 U1$CBB23.L16 U1$CBB23.M4 U1$CBB23.M5 U1$CBB23.M12 U1$CBB23.M13 U1$CBB23.M14 U1$CBB23.N4 U1$CBB23.N7 U1$CBB23.N12 U1$CBB23.N13 U1$CBB23.N14 U1$CBB23.N16 U1$CBB23.P4 U1$CBB23.P7 U1$CBB23.P12 U1$CBB23.P13 U1$CBB23.P14 U1$CBB23.P15 U1$CBB23.R6 U1$CBB23.R13 U1$CBB23.R14 U1$CBB23.R15 U1$CBB23.T6 U1$CBB23.T7 U1$CBB23.T8 U1$CBB23.T14 U1$CBB23.T15 U2$CBB24.7 U6$CBB16/CBB1.9 U6$CBB16/CBB2.9 U6$CBB16/CBB3.9 U6$CBB16/CBB4.9 U6$CBB16/CBB5.9 U6$CBB16/CBB6.9 U6$CBB17/CBB1.9 U6$CBB17/CBB2.9 U6$CBB17/CBB3.9 U6$CBB17/CBB4.9 U6$CBB17/CBB5.9 U6$CBB17/CBB6.9 U6$CBB17/CBB7.9 U6$CBB17/CBB8.9 U6$CBB18/CBB1.9 U6$CBB18/CBB2.9 U6$CBB18/CBB3.9 U6$CBB18/CBB4.9 U6$CBB18/CBB5.9 U6$CBB18/CBB6.9 U6$CBB18/CBB7.9 U6$CBB18/CBB8.9 U6$CBB20/CBB1.9 U6$CBB20/CBB2.9 U6$CBB20/CBB3.9 U6$CBB20/CBB4.9 U6$CBB20/CBB5.9 U6$CBB20/CBB6.9 U6$CBB20/CBB7.9 U6$CBB20/CBB8.9 U10.4 U19$CBB23.9 U98$CBB24.24 U98$CBB24.26 U98$CBB24.27 U98$CBB24.29 U98$CBB24.30 U98$CBB24.32 U98$CBB24.33 U98$CBB24.34 U98$CBB24.36 U98$CBB24.43 U98$CBB24.44 U98$CBB24.45 U98$CBB24.46 U98$CBB24.48 U98$CBB24.52 U98$CBB24.54 U98$CBB24.55 U98$CBB24.57 U98$CBB24.58 U98$CBB24.60 U100$CBB22.A2 U100$CBB22.A3 U100$CBB22.A4 U100$CBB22.A5 U100$CBB22.A6 U100$CBB22.A7 U100$CBB22.A8 U100$CBB22.B1 U100$CBB22.B2 U100$CBB22.B3 U100$CBB22.B4 U100$CBB22.B5 U100$CBB22.B6 U100$CBB22.B7 U100$CBB22.B8 U100$CBB22.C1 U100$CBB22.D1 U100$CBB22.D2 U100$CBB22.D3 U100$CBB22.D6 U100$CBB22.E1 U100$CBB22.E2 U100$CBB22.E3 U100$CBB22.E6 U100$CBB22.E7 U100$CBB22.F7 U100$CBB22.G2 U100$CBB22.G4 U100$CBB22.H2 U100$CBB22.H4 U100$CBB22.H5 U100$CBB22.J1 U100$CBB22.J3 U100$CBB22.J4 U100$CBB22.J5 U100$CBB22.K1 U100$CBB22.K2 U100$CBB22.K3 U100$CBB22.K5 U100$CBB22.L1 U100$CBB22.L3 U100$CBB22.L4 U100$CBB22.L5 U100$CBB22.M2 U100$CBB22.M3 U100$CBB22.M4 U100$CBB22.M6 U100$CBB22.N1 U100$CBB22.N2 U100$CBB22.N3 U100$CBB22.N4 U100$CBB22.N5 U100$CBB22.N6 U100$CBB22.N7 U100$CBB22.P1 U100$CBB22.P3 U100$CBB22.P4 U100$CBB22.P6 U100$CBB22.R1 U100$CBB22.R3 U100$CBB22.R5 U100$CBB22.R6 U100$CBB22.R7 U100$CBB22.T1 U100$CBB22.T2 U100$CBB22.T3 U100$CBB22.T4 U100$CBB22.T5 U100$CBB22.T6 U100$CBB22.U1 U100$CBB22.U3 U100$CBB22.U4 U100$CBB22.U6 U100$CBB22.U7 U100$CBB22.V2 U100$CBB22.V3 U100$CBB22.V5 U100$CBB22.V6 U100$CBB22.V7 U100$CBB22.V8 U111$CBB24.7 X4$CBB22/CBB2.2 X4$CBB22/CBB2.4
copper on no net:
  other v2: 3861.1,5500 3861.1,5531.5

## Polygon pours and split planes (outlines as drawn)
GND on Inner3 (solid, remove dead copper): 3012.9,9829.8 3012.9,3058.2 10690,3058.2 10690,9829.8
GND on Inner1 (solid, remove dead copper): 3012.9,9829.8 3012.9,3058.2 10690,3058.2 10690,9829.8
GND on Bottom Layer (solid, remove dead copper, pour order 68): 3012.9,9829.8 3012.9,3058.2 10690,3058.2 10690,9829.8
3.3VD on Bottom Layer (solid, remove dead copper, pour order 56): 5398.2,4367.1 5152.4,4367.1 5152.4,4390.2 5242,4479.8 5271.7,4479.8 5271.7,4458.6 5325.9,4458.6 5325.9,4706.4 5324.5,4707.8 5183,4707.8 5164.4,4726.4 5164.4,4757.2 5168,4760.9 5476.8,4760.9 5477.9,4759.8 5477.9,4711.9 5476.6,4710.6 5452.3,4710.6 5452.3,4691 5408.2,4691 5401.1,4683.9 5401.1,4412.1 5444.8,4412.1 5452.3,4404.6 5470.6,4404.6 5476.5,4398.8 5476.5,4376.4 5407.5,4376.4
1.2V on Inner4 (solid, remove dead copper): 5400.2,4674.3 5741.5,4674.3 5741.5,4480.8 5416.8,4480.8 5400.2,4497.3
GND on Top Layer (solid, remove dead copper, pour order 62): 3012.9,9829.8 3012.9,3058.2 10690,3058.2 10690,9829.8
$6N165 on Top Layer (solid, remove dead copper, pour order 4): 3846.1,9216.3 3846.1,9144.1 3791.4,9144.1 3777,9129.7 3777,9093 3767.6,9083.6 3629.8,9083.6 3629.8,9270.3 3762.1,9270.3 3777.9,9254.5 3777.9,9225.9 3787.5,9216.3
5.0V on Top Layer (solid, remove dead copper, pour order 6): 3696.5,9324.9 3696.5,9476.3 3775.9,9555.7 3946.5,9555.7 3946.5,9395 3828.7,9395 3754.4,9320.8 3700.6,9320.8
$6N184 on Top Layer (solid, remove dead copper, pour order 8): 4031.9,9252.5 4031.9,9429.2 4091.1,9429.2 4091.1,9252.5
$6N165 on Top Layer (solid, remove dead copper, pour order 10): 3834,8626.9 3906.2,8626.9 3906.3,8572.2 3920.6,8557.8 3957.3,8557.8 3966.7,8548.4 3966.7,8414.6 3780,8414.6 3780,8542.9 3795.8,8558.7 3824.4,8558.7 3834,8568.3
$6N207 on Top Layer (solid, remove dead copper, pour order 16): 3797.8,8812.7 3621.1,8812.7 3621.1,8871.9 3797.8,8871.9
3.3V on Top Layer (solid, remove dead copper, pour order 18): 3725.5,8477.3 3574,8477.3 3494.6,8556.7 3494.6,8727.3 3701.5,8727.3 3701.5,8563.3 3729.6,8535.2 3729.6,8481.4
$6N165 on Inner4 (solid, remove dead copper): 3682.6,9267.7 3682.6,9076.8 3678.3,9072.6 3440,9072.6 3424.5,9057 3424.5,7744.6 3416.5,7736.5 3245.8,7736.5 3243.8,7738.5 3243.8,9111.9 3399.6,9267.7
3.3V on Inner4 (solid, remove dead copper): 3530.9,9027.6 3707.6,9027.6 3707.6,8437.3 3701.6,8431.3 3512.8,8431.3 3506.8,8437.3 3506.8,9003.5
$6N141 on Top Layer (solid, remove dead copper, pour order 20): 3507.5,8922.3 3180.4,8922.3 3179.5,8923.2 3133.3,8923.2 3091.2,8965.4 3091.2,9240.4 3096.4,9245.7 3275.4,9245.7 3275.4,9126.5 3283.9,9118 3396.4,9118 3507.5,9006.9
$6N147 on Top Layer (solid, remove dead copper, pour order 22): 3443.7,9512.4 3450.6,9505.5 3450.6,9142 3436.5,9128 3279.9,9128 3279.9,9294.6 3247.8,9326.8 3247.8,9503.5 3256.7,9512.4
5.0V on Top Layer (solid, remove dead copper, pour order 24): 4062.2,9722.3 4267.9,9722.3 4270.2,9720 4270.2,9613.5 4273.8,9609.9 4267.8,9603.9 4105.2,9603.9 4082.7,9581.4 4052.9,9581.4 3920.8,9449.3 3886.3,9449.3 3886.3,9546.4
5.0V on Top Layer (solid, remove dead copper, pour order 26): 3815.6,9530 3815.6,9635.2 3840,9659.7 3878.7,9659.7 3880.3,9658.1 3880.3,9603.9 3876.3,9599.8 3876.3,9539.8 3877.9,9538.1 3869.9,9530
$6N182 on Top Layer (solid, remove dead copper, pour order 28): 3656.3,8160.6 3679,8183.3 3731.3,8183.3 3731.3,7946.9 3715.6,7931.3 3663.4,7931.3 3656.3,7938.4
$6N165 on Top Layer (solid, remove dead copper, pour order 30): 3473.8,7899.5 3473.8,7877.5 3425,7877.4 3404.7,7857 3404.7,7776.1 3391.2,7762.7 3257.4,7762.7 3257.4,7973.5 3389.7,7973.5 3405.5,7957.7 3405.5,7919.1 3425.2,7899.5
$6N165 on Inner2 (solid, remove dead copper): 3304.4,8366.5 3304.4,8606.3 3309.5,8611.5 3930.5,8611.5 3930.5,8369 3927.9,8366.5
$6N116 on Top Layer (solid, remove dead copper, pour order 32): 3567,7437.4 3567,7379.1 3514.8,7326.9 3436.5,7326.9 3436.5,7405.2 3442.6,7411.3 3502.8,7411.3 3528.9,7437.4
5.0V on Top Layer (solid, remove dead copper, pour order 34): 3555.7,7458.8 3562.6,7451.8 3559.9,7449.1 3548.3,7449.1 3532.9,7464.5 3532.9,7527.7 3526.9,7533.7 3526.9,7536.6 3518,7545.5 3518,7588.1 3523.9,7594 3559,7594 3562.9,7590 3562.9,7466
$6N113 on Top Layer (solid, remove dead copper, pour order 36): 3251.8,7347 3247.8,7343 3169.5,7343 3171.1,7344.6 3171.1,7667.2 3357.2,7667.2 3396.4,7628.1 3396.4,7535.7 3294.3,7535.7 3251.8,7493.3
5.0V on Top Layer (solid, remove dead copper, pour order 40): 3555.7,6947 3562.6,6940 3559.9,6937.3 3548.3,6937.3 3532.9,6952.7 3532.9,7015.9 3526.9,7021.9 3526.9,7024.8 3518,7033.7 3518,7076.3 3523.9,7082.2 3559,7082.2 3562.9,7078.2 3562.9,6954.2
$6N99 on Top Layer (solid, remove dead copper, pour order 44): 3567,6925.6 3567,6867.3 3514.8,6815.1 3436.5,6815.1 3436.5,6893.4 3442.6,6899.4 3502.8,6899.4 3528.9,6925.6
$6N96 on Top Layer (solid, remove dead copper, pour order 46): 3251.8,6835.2 3247.8,6831.2 3169.5,6831.2 3171.1,6832.8 3171.1,7155.4 3357.2,7155.4 3396.4,7116.3 3396.4,7023.9 3294.3,7023.9 3251.8,6981.5
5.0V on Top Layer (solid, remove dead copper, pour order 48): 3555.7,6435.1 3562.6,6428.2 3559.9,6425.5 3548.3,6425.5 3532.9,6440.9 3532.9,6504.1 3526.9,6510.1 3526.9,6513 3518,6521.9 3518,6564.4 3523.9,6570.4 3559,6570.4 3562.9,6566.4 3562.9,6442.4
$6N82 on Top Layer (solid, remove dead copper, pour order 50): 3567,6413.7 3567,6355.5 3514.8,6303.3 3436.5,6303.3 3436.5,6381.6 3442.6,6387.6 3502.8,6387.6 3528.9,6413.7
$6N79 on Top Layer (solid, remove dead copper, pour order 52): 3251.8,6323.4 3247.8,6319.4 3169.5,6319.4 3171.1,6321 3171.1,6643.6 3357.2,6643.6 3396.4,6604.5 3396.4,6512.1 3294.3,6512.1 3251.8,6469.7
3.3VD on Top Layer (solid, remove dead copper, pour order 54): 3328.1,8006.6 3324.2,8010.5 3324.2,8179.5 3355,8210.4 3372.3,8210.4 3423,8261.1 3580.7,8261.1 3580.7,8061.4 3573.1,8053.8 3518.9,8053.8 3471.6,8006.6
3.3V on Inner2 (solid, remove dead copper): 3492.8,8616 3492.8,8854.9 7029.4,8854.9 7029.4,8654.1 4310,8654.1 4271.8,8616
3.3V on Inner4 (solid, remove dead copper): 4546.9,8770.6 4546.9,9238.4 4595.1,9286.6 4595.1,9314.7 4621.2,9340.8 4681.4,9340.8 4695.5,9326.8 4695.5,9272.6 4617.2,9194.3 4617.2,8770.6
3.3V on Inner2 (solid, remove dead copper): 4617.2,9258.5 4617.2,9328.8 4653.3,9364.9 5024.8,9364.9 5088.1,9428.2 7093.9,9428.2 7155.1,9489.4 10578.5,9489.4 10662.9,9405.1 10662.9,9200.3 10660.9,9198.3 10616.4,9198.3 10601,9213.7 10601,9345 10528.8,9417.1 8813.6,9417.1 8751.4,9354.9 8231.3,9354.9 8231.3,9356.9 8167.1,9421.1 7269.6,9421.1 7191.3,9342.8 5175.4,9342.8 5157.3,9324.8 5157.3,9278.6 5109.1,9230.4 4723.6,9230.4 4699.5,9254.5 4621.2,9254.5
3.3V on Inner4 (solid, remove dead copper): 10664.9,9248.5 10664.9,5131.3 10649.9,5116.3 10576.5,5116.3 10576.5,9244.4 10580.6,9248.5
5.0V on Inner4 (solid, remove dead copper): 3854.2,9429.2 3911.6,9486.6 3953.5,9486.6 3962.7,9477.4 3962.7,9401 3980.7,9383 3980.7,9115.9 3943.1,9078.3 3943.1,7391.7 3910.4,7359.1 3802,7359.1 3802,9379 3852.2,9429.2
3.3VD on Inner4 (solid, remove dead copper): 3430.5,6343.5 3430.5,8258.6 3607.2,8258.6 3616.1,8249.6 3616.1,6553.6 3773.5,6396.3 3773.5,6047.5 3759.8,6033.9 3741.7,6033.9 3739.7,6035.9 3738.1,6035.9
5.0V on Inner2 (solid, remove dead copper): 3514.2,7611 3514.2,7519.7 3609.3,7519.7 3626.1,7502.8 3899.6,7502.8 3900.4,7503.6 3900.4,7592 3896.3,7596 3814,7596 3794,7616 3519.1,7616
5.0V on Inner2 (solid, remove dead copper): 3514.2,6587.4 3514.2,6496.1 3609.3,6496.1 3626.1,6479.2 3993.9,6479.2 3993.9,6592.3 3519.1,6592.3
5.0V on Inner2 (solid, remove dead copper): 3822,7551.8 3830.1,7559.8 3842.1,7559.8 3878.3,7596 3926.5,7596 4042.9,7479.5 4042.9,7084 3920.4,7084 3920.4,7246.6 3822,7345
5.0V on Inner4 (solid, remove dead copper): 3946.8,7138.2 3964.9,7156.3 4022.8,7156.3 4028.9,7150.2 4028.9,6234.6 4024.8,6230.6 3946.5,6230.6 3944.5,6232.6 3944.5,7136.2 3946.5,7138.2
5.0V on Inner2 (solid, remove dead copper): 3514.2,7099.2 3514.2,7007.9 3609.3,7007.9 3626.1,6991 4042.1,6991 4042.1,7104.1 3519.1,7104.1
1.8V on Inner4 (solid, remove dead copper): 3059.1,7192.4 3233.7,7192.4 3233.7,6130.2 3141.4,6130.2 3141.4,6937.4 3059.1,7019.7
1.2VA1 on Bottom Layer (solid, remove dead copper, pour order 60): 3960.9,5740.8 3957,5744.7 3944.5,5744.7 3937.3,5751.9 3799.1,5751.9 3777.9,5730.7 3773.8,5730.7 3759.4,5716.3 3749.8,5726 3749.8,5734.7 3753.8,5734.7 3787.9,5768.8 3787.9,5786.9 3789.9,5788.9 3960.6,5788.9 3960.9,5788.5
1.2V on Inner4 (solid, remove dead copper): 3571.1,5899.3 3340.2,6130.2 3239.8,6130.2 3239.8,7425.3 3211.7,7453.4 3079.1,7453.4 3079.1,7696.4 3400.4,7696.4 3420.5,7676.3 3420.5,6339.8 3737.7,6022.5 3737.7,5809 3835.7,5711 3910.8,5711 3944.5,5744.7 3944.5,5750.7 3980.1,5786.3 4050.9,5786.3 4071,5766.2 4071,5604.2 4064.1,5597.3 3903.9,5597.3 3880.6,5574.1 3880.3,5574.1 3869.2,5563 3809.4,5563 3571.1,5801.3
1.8V on Inner2 (solid, remove dead copper): 3049,7172.3 3169.1,7172.3 3171.1,7170.3 3171.1,6934.8 3303.1,6802.9 4428.6,6802.9 4445.3,6785.4 4569,6785.9 4569,6692.4 3059.1,6692.4 3049,6702.5
1.8V on Inner4 (solid, remove dead copper): 4501.5,6768.7 4558.9,6768.7 4558.9,5674.4 4546.9,5662.4 4546.9,5556 4549,5554 4549,5244.8 4460.6,5244.8 4460.6,5855.2 4478.6,5873.2 4478.6,6365.2 4501.5,6388
3.3VD on Inner2 (solid, remove dead copper): 3970.2,5893.8 4774.2,5893.8 4774.2,5580.1 3902.4,5580.1 3892.6,5589.8 3892.6,5668.2 3840.4,5720.4 3722.8,5720.4 3716.6,5726.7 3059.1,5726.7 3059.1,6082 3647.4,6082 3683.5,6118.2 3745.7,6118.2
3.3VD on Inner4 (solid, remove dead copper): 4775.8,5782.9 4787.8,5770.8 4787.8,5564 4761.7,5537.9 4761.7,5377.3 4769.8,5369.3 4769.8,5082.1 4745.7,5082.1 4701.5,5126.3 4701.5,5166.5 4707.5,5172.5 4707.5,5248.8 4665.2,5291.1 4665.2,5768.7 4679.4,5782.9
3.3VD on Inner2 (solid, remove dead copper): 4712.5,5172.5 4882.2,5172.5 4918.3,5136.3 5301.9,5136.3 5303.9,5134.3 5303.9,4997.8 5295.8,4989.8 4852.1,4989.8 4767.8,5074.1 4745.4,5074.1 4712.5,5107
3.3VD on Inner4 (solid, remove dead copper): 5191.4,5116.3 5339.8,5116.3 5350,5106 5350,4844 5375.5,4818.5 5375.5,4689.8 5191.4,4689.8
3.3VD on Inner4 (solid, remove dead copper): 4990.6,5048 5022.8,5048 5066.9,5003.8 5066.9,4777.5 5068.5,4776 5068.5,4759.3 5089,4738.8 5089,4655.8 5073.6,4640.4 5032.8,4640.4 4990.6,4682.6
2.5V on Inner2 (solid, remove dead copper): 3045,6658.3 3050.7,6652.6 3206.6,6652.6 3206.6,6384.3 4262.9,6384.3 4459.9,6187.3 4980.6,6187.3 4980.6,6101.4 4429.1,6101.4 4261.7,6268.8 3045,6268.8
2.5V on Inner4 (solid, remove dead copper): 4920.8,6178.9 5014.7,6178.9 5014.7,5441.5 5056.9,5399.4 5056.9,5212.2 4920.8,5212.2
2.5V on Inner2 (solid, remove dead copper): 5015.3,5285 5046.5,5316.3 5936.5,5316.3 5936.5,5210.8 5014.9,5210.8 5015.3,5211.1
2.5V on Inner4 (solid, remove dead copper): 5870.1,5290.9 5947,5290.9 5947,4425.6 5870.1,4425.6
1.2VA1 on Inner2 (solid, remove dead copper): 3949.1,5754.7 3958.6,5754.7 3964.6,5748.7 3970.6,5748.7 3972.1,5747.3 4068.4,5747.3 4075,5740.7 4078.3,5740.7 4087.4,5731.6 4087.4,5714.6 4073,5714.6 4061.6,5726.1 3959.2,5726.1 3949.1,5736.1
1.2V on Inner2 (solid, remove dead copper): 3478.7,6108.1 3478.7,6262.8 4255.7,6262.8 4426.4,6092.1 4880.2,6092.1 4882.2,6090.1 4916.3,6090.1 4916.3,5971.6 4912.3,5967.6 3902.4,5967.6 3747.8,6122.2 3647.4,6122.2 3623.3,6098.1 3488.7,6098.1
1.2V on Inner4 (solid, remove dead copper): 4679.4,6088.1 4904.8,6088.1 4939.6,6122.8 4939.6,4883.6 4823.8,4883.6 4823.8,5325.8 4802.4,5347.2 4802.4,5770.3 4679.4,5893.3
1.2V on Inner2 (solid, remove dead copper): 4856.1,4967.7 4855.3,4968.5 4855.3,4991.3 5739,4991.3 5739,4876.8 4902.7,4876.8 4856.1,4923.4
1.2V on Inner4 (solid, remove dead copper): 5536.4,4622.2 5536.4,4772.6 5562.9,4799 5583,4799 5594.5,4810.5 5594.5,4994.8 5742.3,4994.8 5742.3,4623.1 5731.5,4612.3 5546.3,4612.3
2.5VA_MIPI_T1 on Bottom Layer (solid, remove dead copper, pour order 62): 5613.9,4391.9 5613.9,4432.7 5614.5,4433.3 5652.2,4433.3 5652.2,4404.8 5644.9,4397.5 5631.8,4397.5 5626.1,4391.9
3.3VD on Inner2 (solid, remove dead copper): 5464.5,4375.4 5463.5,4375.4 5439.5,4399.3 5439.5,4428.8 5378.1,4490.1 5378.1,4517.9 5371,4525.1 5371,4646.4 5808.8,4646.4 5808.8,4532.9 5529.4,4532.9 5464.5,4468 5464.5,4458.6 5479.9,4443.2 5479.9,4390.7
3.3VD on Inner4 (solid, remove dead copper): 5753.5,4566.3 5753.5,5413.3 5866.1,5413.3 5866.1,4566.1 5753.6,4566.1
3.3VD on Inner2 (solid, remove dead copper): 4330.2,5478.1 5003.6,5478.1 5014.3,5467.4 5257.7,5467.4 5267.1,5458 5823.5,5458 5842,5439.5 5842,5323.1 5840,5321.1 5301.9,5321.1 5299.6,5318.8 5221.2,5318.8 5185.4,5354.6 4330.2,5354.6
1.2VA_PLL_T1 on Top Layer (solid, remove dead copper, pour order 56): 5488.2,4455.7 5488.2,4660.8 5514.6,4660.8 5514.6,4466.9 5503.3,4455.7
1.2V on Inner4 (solid, remove dead copper): 5716,4532.2 5817.6,4532.2 5866.1,4483.8 5866.1,4422.6 5897.1,4422.6 6024.7,4295 6024.7,4254.9 5998.7,4228.9 5966.1,4228.9 5896,4299.1 5872.1,4299.1 5771.9,4399.2 5771.9,4483.6 5713.6,4483.6 5713.5,4483.8 5713.5,4529.6
3.3VD on Inner2 (solid, remove dead copper): 4747.7,5164.4 4747.7,5108.2 4737.6,5098.2 4683.4,5098.2 4576,4990.8 4489.7,4990.8 4386.3,4887.4 3952.6,4887.4 3952.6,5164.4
3.3VD on Inner4 (solid, remove dead copper): 4397.6,5162.5 4488.9,5162.5 4506.7,5144.7 4506.7,4219.6 4703.5,4022.8 4703.5,3927.6 4401.6,3927.6 4387.5,3941.7 4387.5,5152.4
3.3VD on Inner2 (solid, remove dead copper): 4448.5,3993.9 4166.4,3993.9 4150.3,4010 4101,4010 4050.7,3959.7 3627.3,3959.7 3593.1,3993.9 3593.1,4104.3 4429.3,4104.3 4448.5,4085.1
3.3VD on Bottom Layer (solid, remove dead copper, pour order 64): 4487.9,4380.2 4497.1,4389.4 4583,4389.4 4589.1,4383.4 4589.1,4367.3 4562.2,4367.3 4550,4355.1 4512.5,4355.1 4503,4345.5 4487.9,4345.5
3.3VD on Inner4 (solid, remove dead copper): 3037,6096.1 3350.2,6096.1 3565,5881.3 3565,5796.9 3777.9,5584.1 3777.9,3630 3764.3,3616.4 3081.1,3616.4 3037,3660.6
3.3VD on Inner2 (solid, remove dead copper): 3594.4,4060.6 4351.7,4060.6 4399.4,4108.3 4597.6,4108.3 4635.8,4146.5 4750.8,4146.5 4795,4190.6 4824,4190.6 4830,4184.6 4904.3,4184.6 4982.6,4106.3 5077.2,4106.3 5619.8,3563.7 5619.8,3130.5 3594.4,3130.5
3.3VD on Inner2 (solid, remove dead copper): 5579.5,3397.7 5604.9,3397.7 5673.3,3329.3 6185.3,3329.3 6220.2,3364.2 6220.2,3414.8 6155.3,3479.7 6145,3479.7 6138.1,3486.7 6138.1,3631.4 6198.3,3691.6 6373.1,3691.6 6403.7,3661 6403.7,3590.9 6613,3381.5 6613,3124.4 6611,3122.4 5583,3122.4 5576.9,3128.5 5576.9,3395.1
1.8V on Bottom Layer (solid, remove dead copper, pour order 66): 5441.4,3679.6 5446.4,3674.6 5496.6,3674.6 5502.6,3668.6 5623.1,3668.6 5627.1,3664.6 5627.1,3628.4 5625.1,3626.4 5472.5,3626.4 5441.4,3657.5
